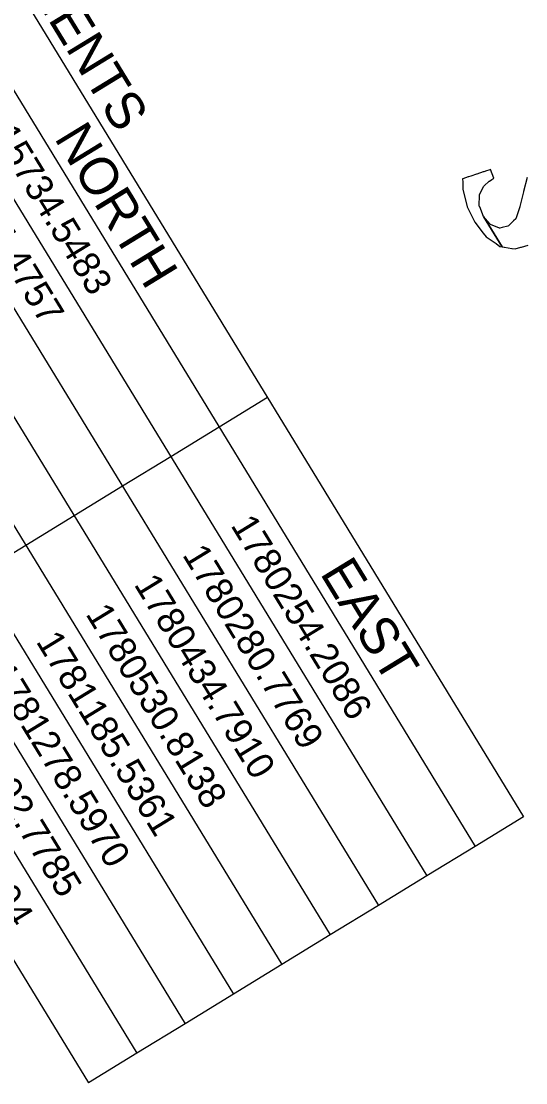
# Model space of a CAD drawing. Extents: x 1753086 to 1770987, y 792577 to 812636.
# Drawn here: x 1764623 to 1765455, y 804619 to 806369 of the extents above; entities that cross this region are included whole.
import ezdxf

# ---------------------------------------------------------------- set-up
doc = ezdxf.new("R2010")
doc.units = 0
for name, color, linetype in [('CTL Sheet Notes CELL', 7, 'Continuous'), ('CTL Sheet Table Cell', 7, 'Continuous'), ('CTL Sheet Text', 7, 'Continuous'), ('Sheet Data Field CELL', 7, 'Continuous')]:
    doc.layers.add(name, color=color, linetype=linetype)

msp = doc.modelspace()

# ---------------------------------------------------------------- linework, layer by layer
at = {"layer": 'CTL Sheet Table Cell'}
for p, q in [((1763632.3, 808034.5), (1765451.3, 805057.5)), ((1763552.6, 807985.8), (1765371.6, 805008.7)), ((1763472.8, 807937.1), (1765291.8, 804960)), ((1763393.1, 807888.4), (1765212.1, 804911.3)), ((1763313.3, 807839.7), (1765132.3, 804862.6)), ((1763233.6, 807790.9), (1765052.6, 804813.9)), ((1763153.9, 807742.2), (1764972.8, 804765.1)), ((1763074.1, 807693.5), (1764893.1, 804716.4)), ((1762994.4, 807644.8), (1764813.4, 804667.7)), ((1762914.6, 807596), (1764733.6, 804619)), ((1765029, 805748.6), (1764949.3, 805699.9)), ((1764949.3, 805699.9), (1764869.6, 805651.1)), ((1764869.6, 805651.1), (1764789.8, 805602.4)), ((1764789.8, 805602.4), (1764710.1, 805553.7)), ((1764710.1, 805553.7), (1764630.3, 805505)), ((1764630.3, 805505), (1764550.6, 805456.2)), ((1765451.3, 805057.5), (1765371.6, 805008.7)), ((1765371.6, 805008.7), (1765291.8, 804960)), ((1765291.8, 804960), (1765212.1, 804911.3)), ((1765212.1, 804911.3), (1765132.3, 804862.6)), ((1765132.3, 804862.6), (1765052.6, 804813.9)), ((1765052.6, 804813.9), (1764972.8, 804765.1)), ((1764972.8, 804765.1), (1764893.1, 804716.4)), ((1764893.1, 804716.4), (1764813.4, 804667.7)), ((1764813.4, 804667.7), (1764733.6, 804619))]:
    msp.add_line(p, q, dxfattribs=at)
at = {"layer": 'Sheet Data Field CELL'}
msp.add_lwpolyline([(1765358.2, 806063.1), (1765370.6, 806037.8), (1765384.5, 806020), (1765389.3, 806013.9), (1765405.8, 806002.5), (1765412.3, 805998), (1765415.7, 805997.4), (1765385.2, 806047.3), (1765378.8, 806063.1), (1765378.2, 806064.5), (1765378.1, 806064.9), (1765378.3, 806082.4), (1765378.4, 806082.9), (1765380.4, 806086.9), (1765385.4, 806097), (1765386.2, 806097.7), (1765394.2, 806105.3), (1765394.8, 806105.7), (1765398.7, 806108.3), (1765402, 806110.5), (1765396.6, 806124.6), (1765393.9, 806123.7), (1765390.1, 806122.4), (1765385.5, 806120.9), (1765384.8, 806120.7), (1765374.3, 806117.1), (1765373.3, 806116.8), (1765364, 806113.7), (1765360.3, 806112.4), (1765360, 806112.4), (1765350.9, 806109.3), (1765350.9, 806109.3), (1765350.6, 806109.2), (1765350.8, 806103.6), (1765351.1, 806098.3), (1765351.3, 806091.6), (1765357.5, 806065.9)], close=True, dxfattribs=at)
msp.add_lwpolyline([(1765457.2, 806111.6), (1765451.1, 806088.4), (1765451, 806088.1), (1765445.1, 806063.7), (1765445, 806063.2), (1765439.9, 806048.4), (1765438.3, 806043.6), (1765434.8, 806040.1), (1765434.3, 806039.6), (1765426.6, 806031.6), (1765425.5, 806031.4), (1765415.7, 806029.1), (1765411.8, 806028.2), (1765411.5, 806028.1), (1765396.9, 806034.1), (1765396.8, 806034.1), (1765395.8, 806035.2), (1765385.2, 806047.3), (1765415.7, 805997.4), (1765419.3, 805996.8), (1765419.6, 805996.8), (1765419.7, 805996.7), (1765431.9, 805994.6), (1765432.4, 805994.6), (1765437.3, 805993.7), (1765446.8, 805996.5), (1765447.8, 805996.8), (1765458.5, 806000)], dxfattribs=at)

# ---------------------------------------------------------------- texts
at = {"layer": 'CTL Sheet Notes CELL'}
for s, p in [('-L- NEW R/W MONUMENTS', (1764222.1, 807099.1)), ('NORTH', (1764676.3, 806176.6)), ('EAST', (1765114.6, 805459.1))]:
    msp.add_text(s, height=62.3, rotation=301.4249, dxfattribs=at).set_placement(p)
at = {"layer": 'CTL Sheet Text'}
for s, p in [('815734.5483', (1764556.5, 806210.4)), ('815734.4757', (1764476.8, 806161.6)), ('1780254.2086', (1764967.3, 805538.1)), ('1780280.7769', (1764887.6, 805489.4)), ('1780434.7910', (1764807.8, 805440.7)), ('1780530.8138', (1764728.1, 805391.9)), ('1781185.5361', (1764646.3, 805346.5)), ('1781278.5970', (1764568.6, 805294.5)), ('1781292.7785', (1764488.8, 805245.8)), ('1780457.8394', (1764409.1, 805197))]:
    msp.add_text(s, height=44.5, rotation=301.4249, dxfattribs=at).set_placement(p)

doc.saveas('drawing.dxf')
